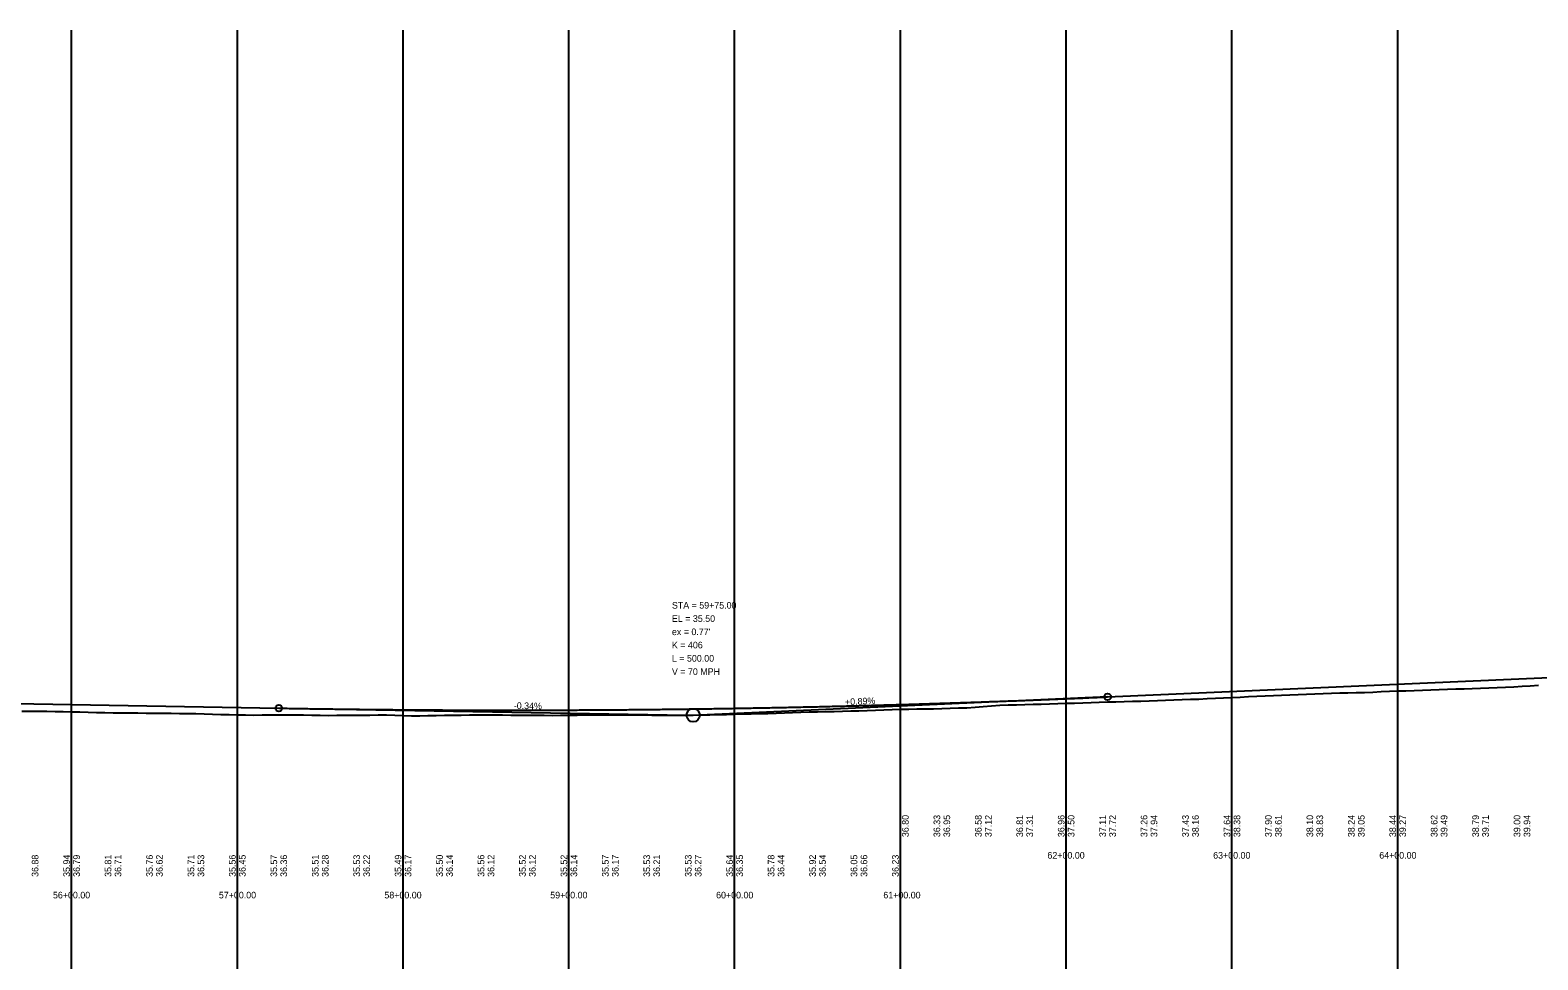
# Model space of a CAD drawing. Extents: x 3880794 to 3915434, y 287517 to 300173.
# Drawn here: x 3904726 to 3905636, y 292943 to 293504 of the extents above; entities that cross this region are included whole.
import ezdxf

# ---------------------------------------------------------------- set-up
doc = ezdxf.new("R2010")
doc.units = 0
for name, color, linetype in [('Level 1', 7, 'Continuous'), ('Level 2', 7, 'Continuous'), ('Level 30', 7, 'Continuous'), ('Level 32', 7, 'Continuous')]:
    doc.layers.add(name, color=color, linetype=linetype)

msp = doc.modelspace()

# ---------------------------------------------------------------- linework, layer by layer
at = {"layer": 'Level 1'}
for p, q in [((3904751.21, 292476.49), (3904751.21, 293504.13)), ((3904851.21, 292476.49), (3904851.21, 293504.13)), ((3904951.21, 292476.49), (3904951.21, 293504.13)), ((3905051.21, 292476.49), (3905051.21, 293504.13)), ((3905151.21, 292476.49), (3905151.21, 293504.13)), ((3905251.21, 292476.49), (3905251.21, 293504.13)), ((3905351.21, 292476.49), (3905351.21, 293504.13)), ((3905451.21, 292476.49), (3905451.21, 293504.13)), ((3905551.21, 292476.49), (3905551.21, 293504.13))]:
    msp.add_line(p, q, dxfattribs=at)
at = {"layer": 'Level 2'}
for p, q in [((3905376.21, 293101.75), (3905851.21, 293122.82)), ((3905376.21, 293101.75), (3905130.21, 293090.84)), ((3904601.21, 293099.71), (3904876.21, 293094.97)), ((3904876.21, 293094.97), (3905122.21, 293090.73))]:
    msp.add_line(p, q, dxfattribs=at)
for points in [[(3905151.21, 293091.35), (3905156.21, 293091.48), (3905161.21, 293091.6), (3905166.21, 293091.72), (3905171.21, 293091.85), (3905176.21, 293092.05), (3905181.21, 293092.19), (3905186.21, 293092.36), (3905191.21, 293092.53), (3905196.21, 293092.7), (3905201.21, 293092.77), (3905206.21, 293092.89), (3905211.21, 293093.01), (3905216.21, 293093.14), (3905221.21, 293093.27), (3905226.21, 293093.39), (3905231.21, 293093.6), (3905236.21, 293093.8), (3905241.21, 293094), (3905246.21, 293094.2), (3905251.21, 293094.31), (3905256.21, 293094.4), (3905261.21, 293094.49), (3905266.21, 293094.57), (3905271.21, 293094.66), (3905276.21, 293094.83), (3905281.21, 293095), (3905286.21, 293095.24), (3905291.21, 293095.27), (3905296.21, 293095.63), (3905301.21, 293096.07), (3905306.21, 293096.44), (3905311.21, 293096.77), (3905316.21, 293096.94), (3905321.21, 293097.01), (3905326.21, 293097.23), (3905331.21, 293097.35), (3905336.21, 293097.48), (3905341.21, 293097.65), (3905346.21, 293097.81), (3905351.21, 293097.95), (3905356.21, 293098.08), (3905361.21, 293098.2), (3905366.21, 293098.35), (3905371.21, 293098.55), (3905376.21, 293098.7), (3905381.21, 293098.84), (3905386.21, 293098.98), (3905391.21, 293099.11), (3905396.21, 293099.24), (3905401.21, 293099.44), (3905406.21, 293099.63), (3905411.21, 293099.8), (3905416.21, 293100.05), (3905421.21, 293100.19), (3905426.21, 293100.32), (3905431.21, 293100.49), (3905436.21, 293100.72), (3905441.21, 293100.95), (3905446.21, 293101.18), (3905451.21, 293101.38), (3905456.21, 293101.66), (3905461.21, 293101.95), (3905466.21, 293102.22), (3905471.21, 293102.46), (3905476.21, 293102.63), (3905481.21, 293102.81), (3905486.21, 293103), (3905491.21, 293103.23), (3905496.21, 293103.45), (3905501.21, 293103.68), (3905506.21, 293103.87), (3905511.21, 293104), (3905516.21, 293104.13), (3905521.21, 293104.25), (3905526.21, 293104.36), (3905531.21, 293104.49), (3905536.21, 293104.65), (3905541.21, 293104.93), (3905546.21, 293105.21), (3905551.21, 293105.38), (3905556.21, 293105.48), (3905561.21, 293105.61), (3905566.21, 293105.88), (3905571.21, 293106.1), (3905576.21, 293106.26), (3905581.21, 293106.42), (3905586.21, 293106.59), (3905591.21, 293106.73), (3905596.21, 293106.92), (3905601.21, 293107.11), (3905606.21, 293107.29), (3905611.21, 293107.5), (3905616.21, 293107.71), (3905621.21, 293107.93), (3905626.21, 293108.15), (3905631.21, 293108.44), (3905636.21, 293108.76)], [(3904721.21, 293093.16), (3904726.21, 293093.13), (3904731.21, 293093.1), (3904736.21, 293093.07), (3904741.21, 293093.04), (3904746.21, 293092.97), (3904751.21, 293092.85), (3904756.21, 293092.73), (3904761.21, 293092.59), (3904766.21, 293092.38), (3904771.21, 293092.27), (3904776.21, 293092.22), (3904781.21, 293092.18), (3904786.21, 293092.15), (3904791.21, 293092.11), (3904796.21, 293092), (3904801.21, 293091.98), (3904806.21, 293091.95), (3904811.21, 293091.93), (3904816.21, 293091.84), (3904821.21, 293091.81), (3904826.21, 293091.7), (3904831.21, 293091.53), (3904836.21, 293091.36), (3904841.21, 293091.23), (3904846.21, 293091.07), (3904851.21, 293090.94), (3904856.21, 293090.88), (3904861.21, 293090.84), (3904866.21, 293090.92), (3904871.21, 293091.04), (3904876.21, 293091.03), (3904881.21, 293090.99), (3904886.21, 293090.87), (3904891.21, 293090.85), (3904896.21, 293090.83), (3904901.21, 293090.7), (3904906.21, 293090.6), (3904911.21, 293090.68), (3904916.21, 293090.76), (3904921.21, 293090.75), (3904926.21, 293090.79), (3904931.21, 293090.83), (3904936.21, 293090.89), (3904941.21, 293090.96), (3904946.21, 293090.78), (3904951.21, 293090.61), (3904956.21, 293090.44), (3904961.21, 293090.42), (3904966.21, 293090.51), (3904971.21, 293090.6), (3904976.21, 293090.68), (3904981.21, 293090.75), (3904986.21, 293090.8), (3904991.21, 293090.85), (3904996.21, 293090.89), (3905001.21, 293090.94), (3905006.21, 293090.91), (3905011.21, 293090.86), (3905016.21, 293090.81), (3905021.21, 293090.81), (3905026.21, 293090.76), (3905031.21, 293090.71), (3905036.21, 293090.67), (3905041.21, 293090.64), (3905046.21, 293090.69), (3905051.21, 293090.77), (3905056.21, 293090.81), (3905061.21, 293090.88), (3905066.21, 293090.95), (3905071.21, 293091.03), (3905076.21, 293091.03), (3905081.21, 293090.98), (3905086.21, 293090.97), (3905091.21, 293090.95), (3905096.21, 293090.94), (3905101.21, 293090.83), (3905106.21, 293090.8), (3905111.21, 293090.76), (3905116.21, 293090.72), (3905121.21, 293090.71), (3905126.21, 293090.81), (3905131.21, 293090.9), (3905136.21, 293090.99), (3905141.21, 293091.08), (3905146.21, 293091.18), (3905151.21, 293091.35)]]:
    msp.add_lwpolyline(points, dxfattribs=at)
for centre, radius in [((3905376.21, 293101.75), 2), ((3904876.21, 293094.97), 2), ((3905126.21, 293090.66), 4)]:
    msp.add_circle(centre, radius, dxfattribs=at)
msp.add_spline([(3904876.21, 293094.97), (3904886.21, 293094.8), (3904896.21, 293094.65), (3904906.21, 293094.51), (3904916.21, 293094.38), (3904926.21, 293094.26), (3904936.21, 293094.16), (3904946.21, 293094.06), (3904956.21, 293093.98), (3904966.21, 293093.92), (3904976.21, 293093.86), (3904986.21, 293093.82), (3904996.21, 293093.79), (3905006.21, 293093.77), (3905016.21, 293093.76), (3905026.21, 293093.77), (3905036.21, 293093.79), (3905046.21, 293093.82), (3905056.21, 293093.86), (3905066.21, 293093.92), (3905076.21, 293093.98), (3905086.21, 293094.06), (3905096.21, 293094.16), (3905106.21, 293094.26), (3905116.21, 293094.38), (3905126.21, 293094.51), (3905136.21, 293094.65), (3905146.21, 293094.8), (3905156.21, 293094.97), (3905166.21, 293095.15), (3905176.21, 293095.34), (3905186.21, 293095.54), (3905196.21, 293095.76), (3905206.21, 293095.99), (3905216.21, 293096.23), (3905226.21, 293096.48), (3905236.21, 293096.75), (3905246.21, 293097.02), (3905256.21, 293097.31), (3905266.21, 293097.61), (3905276.21, 293097.93), (3905286.21, 293098.26), (3905296.21, 293098.59), (3905306.21, 293098.95), (3905316.21, 293099.31), (3905326.21, 293099.68), (3905336.21, 293100.07), (3905346.21, 293100.47), (3905356.21, 293100.89), (3905366.21, 293101.31), (3905376.21, 293101.75)], degree=3, dxfattribs=at)

# ---------------------------------------------------------------- texts
for s, p in [('STA = 59+75.00', (3905113.38, 293155.04)), ('EL = 35.50', (3905113.38, 293147.04)), ("ex = 0.77'", (3905113.38, 293139.04)), ('K = 406', (3905113.38, 293131.04)), ('V = 70 MPH', (3905113.38, 293115.04)), ('L = 500.00', (3905113.38, 293123.04))]:
    msp.add_text(s, height=4, dxfattribs=at).set_placement(p)
for s, rotation, p in [('+0.89%', 2.54018, (3905217.88, 293096.73)), ('-0.34%', 359.01224, (3905017.95, 293094.53))]:
    msp.add_text(s, height=4, rotation=rotation, dxfattribs=at).set_placement(p)
at = {"layer": 'Level 30'}
for s, p in [('62+00.00', (3905339.91, 293004.16)), ('62+00.00', (3905339.91, 293004.16)), ('63+00.00', (3905439.88, 293004.16)), ('64+00.00', (3905540.1, 293004.16)), ('64+00.00', (3905540.1, 293004.16)), ('56+00.00', (3904739.97, 292980.16)), ('56+00.00', (3904739.97, 292980.16)), ('57+00.00', (3904840.06, 292980.16)), ('57+00.00', (3904840.06, 292980.16)), ('58+00.00', (3904939.91, 292980.16)), ('58+00.00', (3904939.91, 292980.16)), ('59+00.00', (3905039.97, 292980.16)), ('59+00.00', (3905039.97, 292980.16)), ('60+00.00', (3905140.03, 292980.16)), ('60+00.00', (3905140.03, 292980.16)), ('61+00.00', (3905240.92, 292980.16)), ('61+00.00', (3905240.92, 292980.16))]:
    msp.add_text(s, height=4, dxfattribs=at).set_placement(p)
at = {"layer": 'Level 32'}
for s, p in [('36.80', (3905256.21, 293017.16)), ('36.33', (3905275.21, 293017.16)), ('36.95', (3905281.21, 293017.16)), ('36.58', (3905300.21, 293017.16)), ('37.12', (3905306.21, 293017.16)), ('36.81', (3905325.21, 293017.16)), ('37.31', (3905331.21, 293017.16)), ('36.96', (3905350.21, 293017.16)), ('37.50', (3905356.21, 293017.16)), ('37.11', (3905375.21, 293017.16)), ('37.72', (3905381.21, 293017.16)), ('37.26', (3905400.21, 293017.16)), ('37.94', (3905406.21, 293017.16)), ('37.43', (3905425.21, 293017.16)), ('38.16', (3905431.21, 293017.16)), ('37.64', (3905450.21, 293017.16)), ('38.38', (3905456.21, 293017.16)), ('37.90', (3905475.21, 293017.16)), ('38.61', (3905481.21, 293017.16)), ('38.10', (3905500.21, 293017.16)), ('38.83', (3905506.21, 293017.16)), ('38.24', (3905525.21, 293017.16)), ('39.05', (3905531.21, 293017.16)), ('38.44', (3905550.21, 293017.16)), ('39.27', (3905556.21, 293017.16)), ('38.62', (3905575.21, 293017.16)), ('39.49', (3905581.21, 293017.16)), ('38.79', (3905600.21, 293017.16)), ('39.71', (3905606.21, 293017.16)), ('39.00', (3905625.21, 293017.16)), ('39.94', (3905631.21, 293017.16)), ('36.88', (3904731.21, 292993.16)), ('35.94', (3904750.21, 292993.16)), ('36.79', (3904756.21, 292993.16)), ('35.81', (3904775.21, 292993.16)), ('36.71', (3904781.21, 292993.16)), ('35.76', (3904800.21, 292993.16)), ('36.62', (3904806.21, 292993.16)), ('35.71', (3904825.21, 292993.16)), ('36.53', (3904831.21, 292993.16)), ('35.56', (3904850.21, 292993.16)), ('36.45', (3904856.21, 292993.16)), ('35.57', (3904875.21, 292993.16)), ('36.36', (3904881.21, 292993.16)), ('35.51', (3904900.21, 292993.16)), ('36.28', (3904906.21, 292993.16)), ('35.53', (3904925.21, 292993.16)), ('36.22', (3904931.21, 292993.16)), ('35.49', (3904950.21, 292993.16)), ('36.17', (3904956.21, 292993.16)), ('35.50', (3904975.21, 292993.16)), ('36.14', (3904981.21, 292993.16)), ('35.56', (3905000.21, 292993.16)), ('36.12', (3905006.21, 292993.16)), ('35.52', (3905025.21, 292993.16)), ('36.12', (3905031.21, 292993.16)), ('35.52', (3905050.21, 292993.16)), ('36.14', (3905056.21, 292993.16)), ('35.57', (3905075.21, 292993.16)), ('36.17', (3905081.21, 292993.16)), ('35.53', (3905100.21, 292993.16)), ('36.21', (3905106.21, 292993.16)), ('35.53', (3905125.21, 292993.16)), ('36.27', (3905131.21, 292993.16)), ('35.64', (3905150.21, 292993.16)), ('36.35', (3905156.21, 292993.16)), ('35.78', (3905175.21, 292993.16)), ('36.44', (3905181.21, 292993.16)), ('35.92', (3905200.21, 292993.16)), ('36.54', (3905206.21, 292993.16)), ('36.05', (3905225.21, 292993.16)), ('36.66', (3905231.21, 292993.16)), ('36.23', (3905250.21, 292993.16))]:
    msp.add_text(s, height=4, rotation=90, dxfattribs=at).set_placement(p)

doc.saveas('drawing.dxf')
